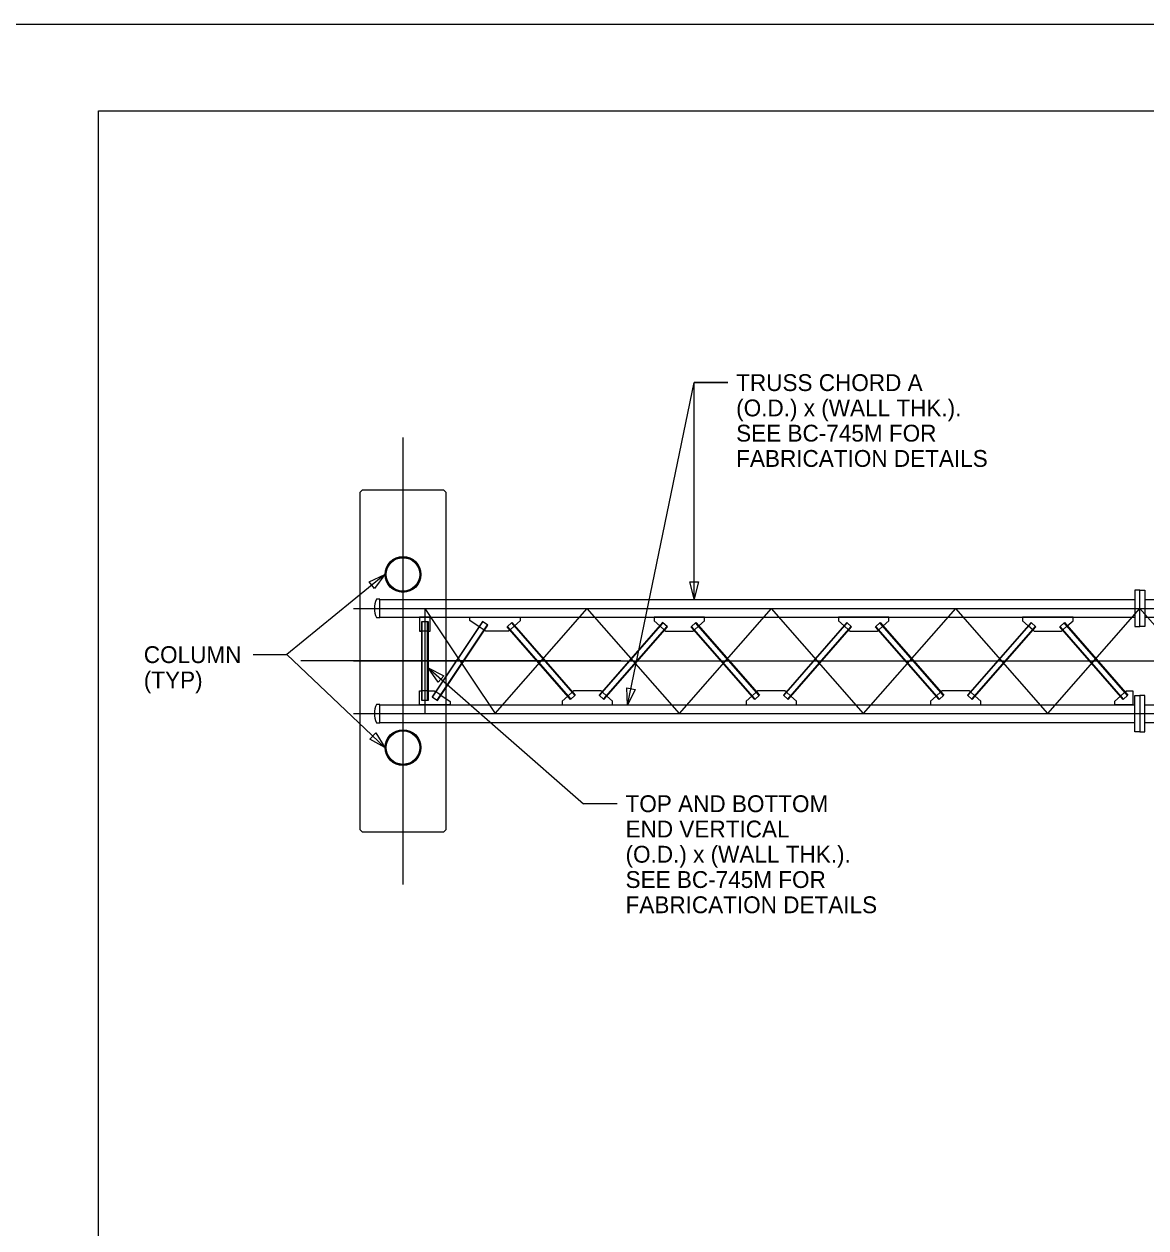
# Model space of a CAD drawing. Extents: x 3831399 to 3833095, y 499014 to 500202.
# Drawn here: x 3832267.3 to 3832461.1, y 499994 to 500202 of the extents above; entities that cross this region are included whole.
import ezdxf

# ---------------------------------------------------------------- set-up
doc = ezdxf.new("R2010")
doc.units = 0
for name, color, linetype in [('0-foundation', 7, 'Continuous'), ('0-truss', 7, 'Continuous'), ('2', 7, 'Continuous'), ('CenterLine', 7, 'Continuous'), ('DIM TXT', 7, 'Continuous'), ('PLT-BNDY', 7, 'Continuous')]:
    doc.layers.add(name, color=color, linetype=linetype)

msp = doc.modelspace()

# ---------------------------------------------------------------- linework, layer by layer
at = {"layer": '0-foundation'}
for p, q in [((3832325.35, 500121.15), (3832325.73, 500121.53)), ((3832325.73, 500121.53), (3832339.75, 500121.53)), ((3832339.75, 500121.53), (3832340.12, 500121.15)), ((3832325.35, 500062.8), (3832325.35, 500121.15)), ((3832340.12, 500121.15), (3832340.12, 500062.8)), ((3832325.73, 500062.42), (3832325.35, 500062.8)), ((3832339.75, 500062.42), (3832325.73, 500062.42)), ((3832340.12, 500062.8), (3832339.75, 500062.42))]:
    msp.add_line(p, q, dxfattribs=at)
at = {"layer": '0-truss'}
for p, q in [((3832328.74, 500102.66), (3832328.17, 500102.66)), ((3832328.74, 500102.58), (3832459.19, 500102.58)), ((3832460.05, 500104.22), (3832459.19, 500104.22)), ((3832459.19, 500104.22), (3832459.19, 500097.92)), ((3832460.05, 500097.92), (3832460.05, 500104.22)), ((3832460.05, 500097.92), (3832460.05, 500104.22)), ((3832460.05, 500104.22), (3832460.9, 500104.22)), ((3832460.9, 500104.22), (3832460.9, 500097.92)), ((3832460.9, 500102.58), (3832618.33, 500102.58)), ((3832328.74, 500099.55), (3832459.19, 500099.55)), ((3832335.98, 500085.15), (3832335.98, 500098.8)), ((3832335.98, 500098.8), (3832337.07, 500098.8)), ((3832336.06, 500085.15), (3832336.06, 500098.8)), ((3832336.99, 500085.15), (3832336.99, 500098.8)), ((3832337.07, 500098.8), (3832337.07, 500085.15)), ((3832346.48, 500098.8), (3832337.79, 500085.76)), ((3832337.85, 500085.72), (3832346.54, 500098.75)), ((3832345.88, 500097.9), (3832344.29, 500098.96)), ((3832347.39, 500098.19), (3832346.48, 500098.8)), ((3832350.71, 500097.89), (3832351.53, 500098.61)), ((3832351.47, 500098.56), (3832362.45, 500086.01)), ((3832351.53, 500098.61), (3832362.51, 500086.06)), ((3832353.01, 500098.9), (3832352.02, 500098.04)), ((3832377.6, 500098.61), (3832366.62, 500086.06)), ((3832366.68, 500086.01), (3832377.66, 500098.56)), ((3832376.12, 500098.9), (3832377.11, 500098.04)), ((3832378.42, 500097.89), (3832377.6, 500098.61)), ((3832382.53, 500097.89), (3832383.35, 500098.61)), ((3832394.28, 500086.01), (3832383.3, 500098.56)), ((3832383.35, 500098.61), (3832394.33, 500086.06)), ((3832383.85, 500098.04), (3832384.83, 500098.9)), ((3832409.43, 500098.61), (3832398.45, 500086.06)), ((3832398.51, 500086.01), (3832409.49, 500098.56)), ((3832407.95, 500098.9), (3832408.93, 500098.04)), ((3832410.25, 500097.89), (3832409.43, 500098.61)), ((3832414.36, 500097.89), (3832415.18, 500098.61)), ((3832426.1, 500086.01), (3832415.12, 500098.56)), ((3832415.18, 500098.61), (3832426.16, 500086.06)), ((3832415.68, 500098.04), (3832416.66, 500098.9)), ((3832441.25, 500098.61), (3832430.27, 500086.06)), ((3832430.33, 500086.01), (3832441.31, 500098.56)), ((3832439.77, 500098.9), (3832440.76, 500098.04)), ((3832442.07, 500097.89), (3832441.25, 500098.61)), ((3832446.19, 500097.89), (3832447.01, 500098.61)), ((3832457.93, 500086.01), (3832446.95, 500098.56)), ((3832447.01, 500098.61), (3832457.99, 500086.06)), ((3832447.5, 500098.04), (3832448.49, 500098.9)), ((3832460.9, 500099.55), (3832618.33, 500099.55)), ((3832337.07, 500097.14), (3832335.98, 500097.14)), ((3832338.63, 500085.2), (3832347.32, 500098.23)), ((3832338.7, 500085.15), (3832347.39, 500098.19)), ((3832346.79, 500097.3), (3832345.88, 500097.9)), ((3832347.03, 500097.14), (3832346.79, 500097.3)), ((3832350.99, 500097.14), (3832347.03, 500097.14)), ((3832361.69, 500085.34), (3832350.71, 500097.89)), ((3832350.76, 500097.94), (3832361.74, 500085.39)), ((3832351.2, 500097.32), (3832350.99, 500097.14)), ((3832352.02, 500098.04), (3832351.2, 500097.32)), ((3832367.38, 500085.39), (3832378.36, 500097.94)), ((3832367.44, 500085.34), (3832378.42, 500097.89)), ((3832377.92, 500097.32), (3832377.11, 500098.04)), ((3832377.92, 500097.32), (3832378.14, 500097.14)), ((3832393.51, 500085.34), (3832382.53, 500097.89)), ((3832393.57, 500085.39), (3832382.59, 500097.94)), ((3832382.82, 500097.14), (3832383.03, 500097.32)), ((3832383.85, 500098.04), (3832383.03, 500097.32)), ((3832399.21, 500085.39), (3832410.19, 500097.94)), ((3832399.27, 500085.34), (3832410.25, 500097.89)), ((3832409.75, 500097.32), (3832408.93, 500098.04)), ((3832409.75, 500097.32), (3832409.97, 500097.14)), ((3832425.34, 500085.34), (3832414.36, 500097.89)), ((3832425.4, 500085.39), (3832414.42, 500097.94)), ((3832414.64, 500097.14), (3832414.86, 500097.32)), ((3832415.68, 500098.04), (3832414.86, 500097.32)), ((3832431.04, 500085.39), (3832442.02, 500097.94)), ((3832431.09, 500085.34), (3832442.07, 500097.89)), ((3832441.58, 500097.32), (3832440.76, 500098.04)), ((3832441.58, 500097.32), (3832441.79, 500097.14)), ((3832457.17, 500085.34), (3832446.19, 500097.89)), ((3832457.23, 500085.39), (3832446.25, 500097.94)), ((3832446.47, 500097.14), (3832446.68, 500097.32)), ((3832447.5, 500098.04), (3832446.68, 500097.32)), ((3832459.19, 500097.92), (3832460.05, 500097.92)), ((3832460.9, 500097.92), (3832460.05, 500097.92)), ((3832337.07, 500086.81), (3832335.98, 500086.81)), ((3832338.15, 500086.81), (3832338.39, 500086.65)), ((3832339.29, 500086.05), (3832338.39, 500086.65)), ((3832339.29, 500086.05), (3832340.91, 500084.97)), ((3832361.19, 500085.91), (3832360.21, 500085.05)), ((3832362.01, 500086.63), (3832361.19, 500085.91)), ((3832362.51, 500086.06), (3832361.69, 500085.34)), ((3832362.23, 500086.81), (3832362.01, 500086.63)), ((3832366.62, 500086.06), (3832367.44, 500085.34)), ((3832367.12, 500086.63), (3832366.9, 500086.81)), ((3832367.94, 500085.91), (3832367.12, 500086.63)), ((3832368.92, 500085.05), (3832367.94, 500085.91)), ((3832393.02, 500085.91), (3832392.03, 500085.05)), ((3832393.84, 500086.63), (3832393.02, 500085.91)), ((3832394.33, 500086.06), (3832393.51, 500085.34)), ((3832394.05, 500086.81), (3832393.84, 500086.63)), ((3832398.45, 500086.06), (3832399.27, 500085.34)), ((3832398.94, 500086.63), (3832398.73, 500086.81)), ((3832399.76, 500085.91), (3832398.94, 500086.63)), ((3832400.75, 500085.05), (3832399.76, 500085.91)), ((3832424.85, 500085.91), (3832423.86, 500085.05)), ((3832425.67, 500086.63), (3832424.85, 500085.91)), ((3832426.16, 500086.06), (3832425.34, 500085.34)), ((3832425.88, 500086.81), (3832425.67, 500086.63)), ((3832430.27, 500086.06), (3832431.09, 500085.34)), ((3832430.77, 500086.63), (3832430.56, 500086.81)), ((3832431.59, 500085.91), (3832430.77, 500086.63)), ((3832432.58, 500085.05), (3832431.59, 500085.91)), ((3832455.69, 500085.05), (3832456.67, 500085.91)), ((3832457.49, 500086.63), (3832456.67, 500085.91)), ((3832457.99, 500086.06), (3832457.17, 500085.34)), ((3832457.49, 500086.63), (3832457.71, 500086.81)), ((3832457.71, 500086.81), (3832458.81, 500086.81)), ((3832458.81, 500086.81), (3832458.81, 500086.81)), ((3832458.81, 500086.81), (3832458.81, 500084.4)), ((3832459.19, 500086.03), (3832460.05, 500086.03)), ((3832459.19, 500079.73), (3832459.19, 500086.03)), ((3832460.05, 500086.03), (3832460.05, 500079.73)), ((3832460.9, 500086.03), (3832460.05, 500086.03)), ((3832460.05, 500086.03), (3832460.05, 500079.73)), ((3832460.9, 500079.73), (3832460.9, 500086.03)), ((3832328.74, 500084.47), (3832328.17, 500084.47)), ((3832328.74, 500084.4), (3832459.19, 500084.4)), ((3832337.07, 500085.15), (3832335.98, 500085.15)), ((3832337.79, 500085.76), (3832338.7, 500085.15)), ((3832460.9, 500084.4), (3832618.33, 500084.4)), ((3832328.74, 500081.37), (3832459.19, 500081.37)), ((3832460.05, 500079.73), (3832459.19, 500079.73)), ((3832460.05, 500079.73), (3832460.9, 500079.73)), ((3832460.9, 500081.37), (3832618.33, 500081.37))]:
    msp.add_line(p, q, dxfattribs=at)
for points in [[(3832328.17, 500099.48), (3832328.74, 500099.48), (3832328.74, 500102.66)], [(3832337.07, 500097.14), (3832337.45, 500097.14), (3832337.45, 500099.55), (3832335.6, 500099.55)], [(3832335.6, 500099.55), (3832335.6, 500097.14), (3832335.98, 500097.14)], [(3832344.29, 500098.96), (3832344.29, 500099.55), (3832353.01, 500099.55), (3832353.01, 500098.9)], [(3832384.83, 500098.9), (3832384.83, 500099.55), (3832376.12, 500099.55), (3832376.12, 500098.9)], [(3832416.66, 500098.9), (3832416.66, 500099.55), (3832407.95, 500099.55), (3832407.95, 500098.9)], [(3832448.49, 500098.9), (3832448.49, 500099.55), (3832439.77, 500099.55), (3832439.77, 500098.9)], [(3832335.98, 500097.14), (3832335.77, 500097.14)], [(3832378.14, 500097.14), (3832382.82, 500097.14)], [(3832409.97, 500097.14), (3832414.64, 500097.14)], [(3832441.79, 500097.14), (3832446.47, 500097.14)], [(3832340.91, 500084.97), (3832340.91, 500084.4), (3832335.6, 500084.4), (3832335.6, 500086.81), (3832335.98, 500086.81)], [(3832337.07, 500086.81), (3832338.15, 500086.81)], [(3832366.9, 500086.81), (3832362.23, 500086.81)], [(3832398.73, 500086.81), (3832394.05, 500086.81)], [(3832430.56, 500086.81), (3832425.88, 500086.81)], [(3832328.17, 500081.29), (3832328.74, 500081.29), (3832328.74, 500084.47)], [(3832360.21, 500085.05), (3832360.21, 500084.4), (3832368.92, 500084.4), (3832368.92, 500085.05)], [(3832392.03, 500085.05), (3832392.03, 500084.4), (3832400.75, 500084.4), (3832400.75, 500085.05)], [(3832423.86, 500085.05), (3832423.86, 500084.4), (3832432.58, 500084.4), (3832432.58, 500085.05)], [(3832458.81, 500084.4), (3832455.69, 500084.4), (3832455.69, 500085.05)]]:
    msp.add_lwpolyline(points, dxfattribs=at)
for centre, radius in [((3832332.74, 500106.94), 3.1), ((3832332.74, 500106.94), 3.03), ((3832332.74, 500106.94), 2.89), ((3832332.74, 500077.01), 3.1), ((3832332.74, 500077.01), 3.03), ((3832332.74, 500077.01), 2.89)]:
    msp.add_circle(centre, radius, dxfattribs=at)
for centre in [(3832331.28, 500101.07), (3832331.28, 500082.88)]:
    msp.add_arc(centre, 3.49, 152.944, 207.056, dxfattribs=at)
at = {"layer": '2'}
for p, q in [((3832280.16, 499623.03), (3832280.16, 500187.03)), ((3832280.16, 500187.03), (3833066.16, 500187.03))]:
    msp.add_line(p, q, dxfattribs=at)
at = {"layer": 'CenterLine'}
for p, q in [((3832332.74, 500130.62), (3832332.74, 500053.33)), ((3832324.19, 500101.07), (3832755.03, 500101.07)), ((3832336.53, 500101.07), (3832348.65, 500082.88)), ((3832336.53, 500101.07), (3832336.53, 500082.88)), ((3832348.65, 500082.88), (3832364.56, 500101.07)), ((3832380.48, 500082.88), (3832364.56, 500101.07)), ((3832380.48, 500082.88), (3832396.39, 500101.07)), ((3832412.3, 500082.88), (3832396.39, 500101.07)), ((3832412.3, 500082.88), (3832428.22, 500101.07)), ((3832444.13, 500082.88), (3832428.22, 500101.07)), ((3832444.13, 500082.88), (3832460.05, 500101.07)), ((3832475.96, 500082.88), (3832460.05, 500101.07)), ((3832370.38, 500091.98), (3832315.1, 500091.98)), ((3832324.19, 500091.98), (3832755.03, 500091.98)), ((3832324.19, 500082.88), (3832755.03, 500082.88))]:
    msp.add_line(p, q, dxfattribs=at)
at = {"layer": 'DIM TXT'}
for p, q in [((3832371.54, 500084.34), (3832383.02, 500140.07)), ((3832383.02, 500140.07), (3832388.84, 500140.07)), ((3832383.04, 500102.74), (3832383.02, 500140.07)), ((3832388.84, 500140.07), (3832383.02, 500140.07)), ((3832388.84, 500140.07), (3832383.02, 500140.07)), ((3832329.63, 500106.94), (3832312.7, 500093.07)), ((3832306.88, 500093.07), (3832312.7, 500093.07)), ((3832306.88, 500093.07), (3832312.7, 500093.07)), ((3832329.63, 500077.01), (3832312.7, 500093.07)), ((3832337.11, 500090.78), (3832363.91, 500067.31)), ((3832369.73, 500067.31), (3832363.91, 500067.31))]:
    msp.add_line(p, q, dxfattribs=at)
for points in [[(3832326.92, 500105.66), (3832329.63, 500106.94), (3832327.84, 500104.53)], [(3832383.77, 500105.65), (3832383.04, 500102.74), (3832382.31, 500105.65)], [(3832338.82, 500088.31), (3832337.11, 500090.78), (3832339.78, 500089.41)], [(3832372.84, 500087.04), (3832371.54, 500084.34), (3832371.42, 500087.34)], [(3832328.02, 500079.54), (3832329.63, 500077.01), (3832327.02, 500078.48)]]:
    msp.add_lwpolyline(points, close=True, dxfattribs=at)
at = {"layer": 'PLT-BNDY'}
msp.add_lwpolyline([(3832240.16, 500202.03), (3833081.16, 500202.03), (3833081.16, 499608.03), (3832240.16, 499608.03)], close=True, dxfattribs=at)

# ---------------------------------------------------------------- texts
at = {"layer": 'DIM TXT'}
for s, height, p in [('TRUSS CHORD A', 2.9099, (3832390.3, 500138.62)), ('(O.D.) x (WALL THK.).', 2.9099, (3832390.3, 500134.25)), ('SEE BC-745M FOR', 2.9099, (3832390.3, 500129.89)), ('FABRICATION DETAILS', 2.9099, (3832390.3, 500125.52)), ('COLUMN', 2.91, (3832287.96, 500091.62)), ('(TYP)', 2.91, (3832287.96, 500087.25)), ('TOP AND BOTTOM', 2.9099, (3832371.19, 500065.86)), ('END VERTICAL', 2.9099, (3832371.19, 500061.49)), ('(O.D.) x (WALL THK.).', 2.9099, (3832371.19, 500057.13)), ('SEE BC-745M FOR', 2.9099, (3832371.19, 500052.76)), ('FABRICATION DETAILS', 2.9099, (3832371.19, 500048.4))]:
    msp.add_text(s, height=height, dxfattribs=at).set_placement(p)

doc.saveas('drawing.dxf')
